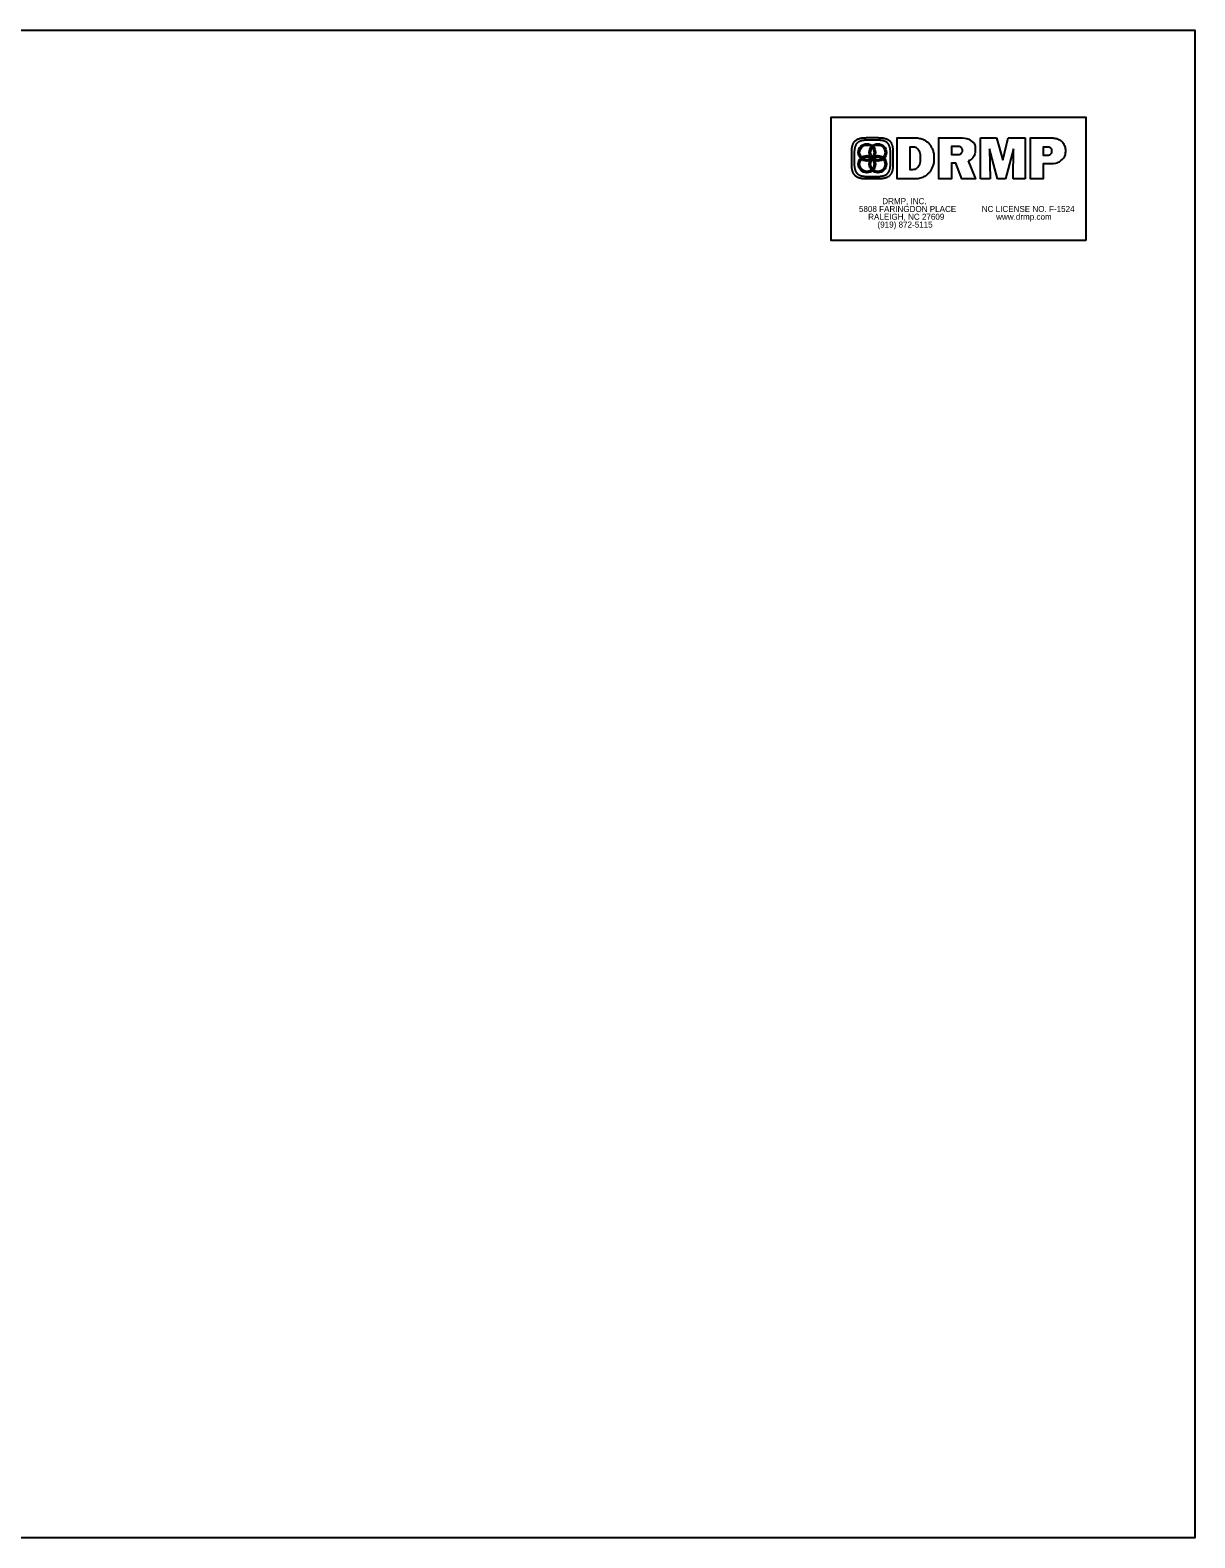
# Model space of a CAD drawing. Extents: x 0.1 to 1.42, y -0.88 to -0.03.
import ezdxf

# ---------------------------------------------------------------- set-up
doc = ezdxf.new("R2010")
doc.units = 0
for name, color, linetype in [('Pattern 1', 7, 'Continuous'), ('Pattern 2', 7, 'Continuous'), ('Sheet Plan CELL', 7, 'Continuous'), ('Sheet Plot Border Inside CELL', 7, 'Continuous')]:
    doc.layers.add(name, color=color, linetype=linetype)

msp = doc.modelspace()

# ---------------------------------------------------------------- linework, layer by layer
at = {"layer": 'Pattern 1'}
for p, q in [((1.23106, -0.09323), (1.23782, -0.09323)), ((1.29547, -0.11658), (1.29547, -0.09325)), ((1.29547, -0.09325), (1.30465, -0.09325)), ((1.30465, -0.09325), (1.30815, -0.10599)), ((1.30815, -0.10599), (1.31123, -0.09325)), ((1.31123, -0.09325), (1.32081, -0.09325)), ((1.32081, -0.09325), (1.32081, -0.11658)), ((1.22278, -0.10827), (1.22278, -0.1015)), ((1.22421, -0.10192), (1.22421, -0.10785)), ((1.23741, -0.09465), (1.23148, -0.09465)), ((1.24467, -0.10785), (1.24467, -0.10192)), ((1.2461, -0.1015), (1.2461, -0.10827)), ((1.30523, -0.11658), (1.30068, -0.09947)), ((1.30068, -0.09947), (1.30093, -0.11658)), ((1.3142, -0.09947), (1.30975, -0.11658)), ((1.31408, -0.11658), (1.3142, -0.09947)), ((1.23782, -0.11654), (1.23106, -0.11654)), ((1.23148, -0.11512), (1.23741, -0.11512)), ((1.30093, -0.11658), (1.29547, -0.11658)), ((1.30975, -0.11658), (1.30523, -0.11658)), ((1.32081, -0.11658), (1.31408, -0.11658))]:
    msp.add_line(p, q, dxfattribs=at)
for points in [[(1.25717, -0.11658), (1.24851, -0.11658), (1.24851, -0.09325), (1.25749, -0.09325)], [(1.28851, -0.10639), (1.29272, -0.11658), (1.28505, -0.11658), (1.28159, -0.10773), (1.27914, -0.10773), (1.27914, -0.11658), (1.27205, -0.11658), (1.27205, -0.09325), (1.28344, -0.09325)], [(1.33508, -0.10808), (1.33094, -0.10808), (1.33094, -0.11658), (1.32379, -0.11658), (1.32379, -0.09325), (1.33373, -0.09325)], [(1.25749, -0.09861), (1.25566, -0.09861), (1.25566, -0.11113), (1.25727, -0.11113)], [(1.28244, -0.09823), (1.27914, -0.09823), (1.27914, -0.10279), (1.28254, -0.10279)], [(1.33329, -0.09852), (1.33094, -0.09852), (1.33094, -0.1031), (1.33286, -0.1031)]]:
    msp.add_lwpolyline(points, dxfattribs=at)
for points, degree in [([(1.22278, -0.1015), (1.22278, -0.09695), (1.22651, -0.09323), (1.23106, -0.09323)], 2), ([(1.23782, -0.09323), (1.24238, -0.09323), (1.2461, -0.09695), (1.2461, -0.1015)], 2), ([(1.25749, -0.09325), (1.2589, -0.09325), (1.26016, -0.09338), (1.26128, -0.09363), (1.2624, -0.09388), (1.26337, -0.09427), (1.26421, -0.09479), (1.26581, -0.0958), (1.26705, -0.09719), (1.26793, -0.09896), (1.26881, -0.10072), (1.26925, -0.10271), (1.26925, -0.10491), (1.26925, -0.10686), (1.26886, -0.10868), (1.26808, -0.11038), (1.26731, -0.11207), (1.26625, -0.11342), (1.26491, -0.11443), (1.26392, -0.11516), (1.26279, -0.11571), (1.26154, -0.11606), (1.26028, -0.11641), (1.25883, -0.11658), (1.25717, -0.11658)], 3), ([(1.28344, -0.09325), (1.2865, -0.09325), (1.28878, -0.09382), (1.2903, -0.09495), (1.29183, -0.09608), (1.29259, -0.09779), (1.29259, -0.10007), (1.29259, -0.10164), (1.29224, -0.10297), (1.29154, -0.10406), (1.29085, -0.10514), (1.28984, -0.10592), (1.28851, -0.10639)], 3), ([(1.33373, -0.09325), (1.33529, -0.09325), (1.33658, -0.09335), (1.3376, -0.09354), (1.33862, -0.09373), (1.33947, -0.09403), (1.34015, -0.09445), (1.34125, -0.09514), (1.34208, -0.09601), (1.34264, -0.09706), (1.34321, -0.09811), (1.34349, -0.09931), (1.34349, -0.10064), (1.34349, -0.10286), (1.34272, -0.10466), (1.34117, -0.10603), (1.33963, -0.1074), (1.3376, -0.10808), (1.33508, -0.10808)], 3), ([(1.23148, -0.09465), (1.22748, -0.09465), (1.22421, -0.09792), (1.22421, -0.10192)], 2), ([(1.24467, -0.10192), (1.24467, -0.09792), (1.24141, -0.09465), (1.23741, -0.09465)], 2), ([(1.25727, -0.11113), (1.25861, -0.11113), (1.25968, -0.11055), (1.26049, -0.1094), (1.26129, -0.10825), (1.2617, -0.10672), (1.2617, -0.10481), (1.2617, -0.10291), (1.26132, -0.10141), (1.26055, -0.10029), (1.25979, -0.09917), (1.25877, -0.09861), (1.25749, -0.09861)], 3), ([(1.28254, -0.10279), (1.28337, -0.10279), (1.28405, -0.10258), (1.28457, -0.10215), (1.2851, -0.10172), (1.28536, -0.10118), (1.28536, -0.10051), (1.28536, -0.09974), (1.28512, -0.09917), (1.28463, -0.0988), (1.28415, -0.09842), (1.28341, -0.09823), (1.28244, -0.09823)], 3), ([(1.33286, -0.1031), (1.33382, -0.1031), (1.33457, -0.1029), (1.33511, -0.10249), (1.33565, -0.10209), (1.33592, -0.10153), (1.33592, -0.1008), (1.33592, -0.10007), (1.33569, -0.09951), (1.33524, -0.09911), (1.33479, -0.09872), (1.33414, -0.09852), (1.33329, -0.09852)], 3), ([(1.23106, -0.11654), (1.22651, -0.11654), (1.22278, -0.11282), (1.22278, -0.10827)], 2), ([(1.22421, -0.10785), (1.22421, -0.11185), (1.22748, -0.11512), (1.23148, -0.11512)], 2), ([(1.23741, -0.11512), (1.24141, -0.11512), (1.24467, -0.11185), (1.24467, -0.10785)], 2), ([(1.2461, -0.10827), (1.2461, -0.11282), (1.24238, -0.11654), (1.23782, -0.11654)], 2)]:
    msp.add_open_spline(points, degree=degree, dxfattribs=at)
at = {"layer": 'Pattern 2'}
for centre, radius in [((1.23134, -0.10157), 0.00488), ((1.23134, -0.10157), 0.00415), ((1.23755, -0.10157), 0.00488), ((1.23755, -0.10157), 0.00415), ((1.23134, -0.1082), 0.00488), ((1.23134, -0.1082), 0.00415), ((1.23755, -0.1082), 0.00488), ((1.23755, -0.1082), 0.00415)]:
    msp.add_circle(centre, radius, dxfattribs=at)
at = {"layer": 'Sheet Plan CELL'}
msp.add_lwpolyline([(1.35515, -0.15135), (1.21112, -0.15135), (1.21112, -0.08158), (1.35515, -0.08158)], close=True, dxfattribs=at)
at = {"layer": 'Sheet Plot Border Inside CELL'}
msp.add_lwpolyline([(0.10046, -0.0325), (1.41667, -0.0325), (1.41667, -0.88416), (0.10046, -0.88416)], close=True, dxfattribs=at)

# ---------------------------------------------------------------- texts
at = {"layer": 'Pattern 2'}
for s, height, p in [('DRMP, INC.', 0.003408, (1.24004, -0.1308)), ('5808 FARINGDON PLACE', 0.0034076, (1.22687, -0.13521)), ('RALEIGH, NC 27609', 0.0034076, (1.23207, -0.13962)), ('NC LICENSE NO. F-1524', 0.0034076, (1.29627, -0.13521)), ('www.drmp.com', 0.0034076, (1.30438, -0.13962)), ('(919) 872-5115', 0.0034076, (1.23735, -0.14403))]:
    msp.add_text(s, height=height, rotation=360, dxfattribs=at).set_placement(p)

doc.saveas('drawing.dxf')
